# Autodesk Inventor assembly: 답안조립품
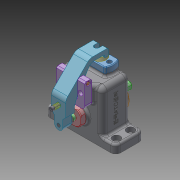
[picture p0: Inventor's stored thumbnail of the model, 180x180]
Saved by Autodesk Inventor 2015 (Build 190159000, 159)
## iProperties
Created: 2023-12
Part Number: 답안조립품
Document SubType Name: Assembly
Designer: user
Author: user
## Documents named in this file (14)
- C:\Users\user\Desktop\731208V1017\답안조립품.iam
- C:\Users\user\Desktop\731208V1017\가공품.ipt
- C:\Users\user\Desktop\731208V1017\가이드 부시.ipt
- C:\Users\user\Desktop\731208V1017\고정대.ipt
- C:\Users\user\Desktop\731208V1017\본체.ipt
- C:\Users\user\Desktop\731208V1017\브라켓.ipt
- C:\Users\user\Desktop\731208V1017\스프링.ipt
- C:\Users\user\Desktop\731208V1017\육각 머리 볼트 M6 x 12.ipt
- C:\Users\user\Desktop\731208V1017\육각 소켓 머리 볼트 M3 x 8.ipt
- C:\Users\user\Desktop\731208V1017\육각 소켓 머리 볼트 M3 x 30.ipt
- C:\Users\user\Desktop\731208V1017\조절 부시.ipt
- C:\Users\user\Desktop\731208V1017\클램프 샤프트.ipt
- C:\Users\user\Desktop\731208V1017\클램프.ipt
- C:\Users\user\Desktop\731208V1017\핀.ipt
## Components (4 placed, 4 different names)
1. 가공품:1
2. 가이드 부시:1 — 각도:1
3. 고정대:1
4. 핀:1
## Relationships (1: Angle 1)
- 각도:1 [Angle]: 가이드 부시:1
